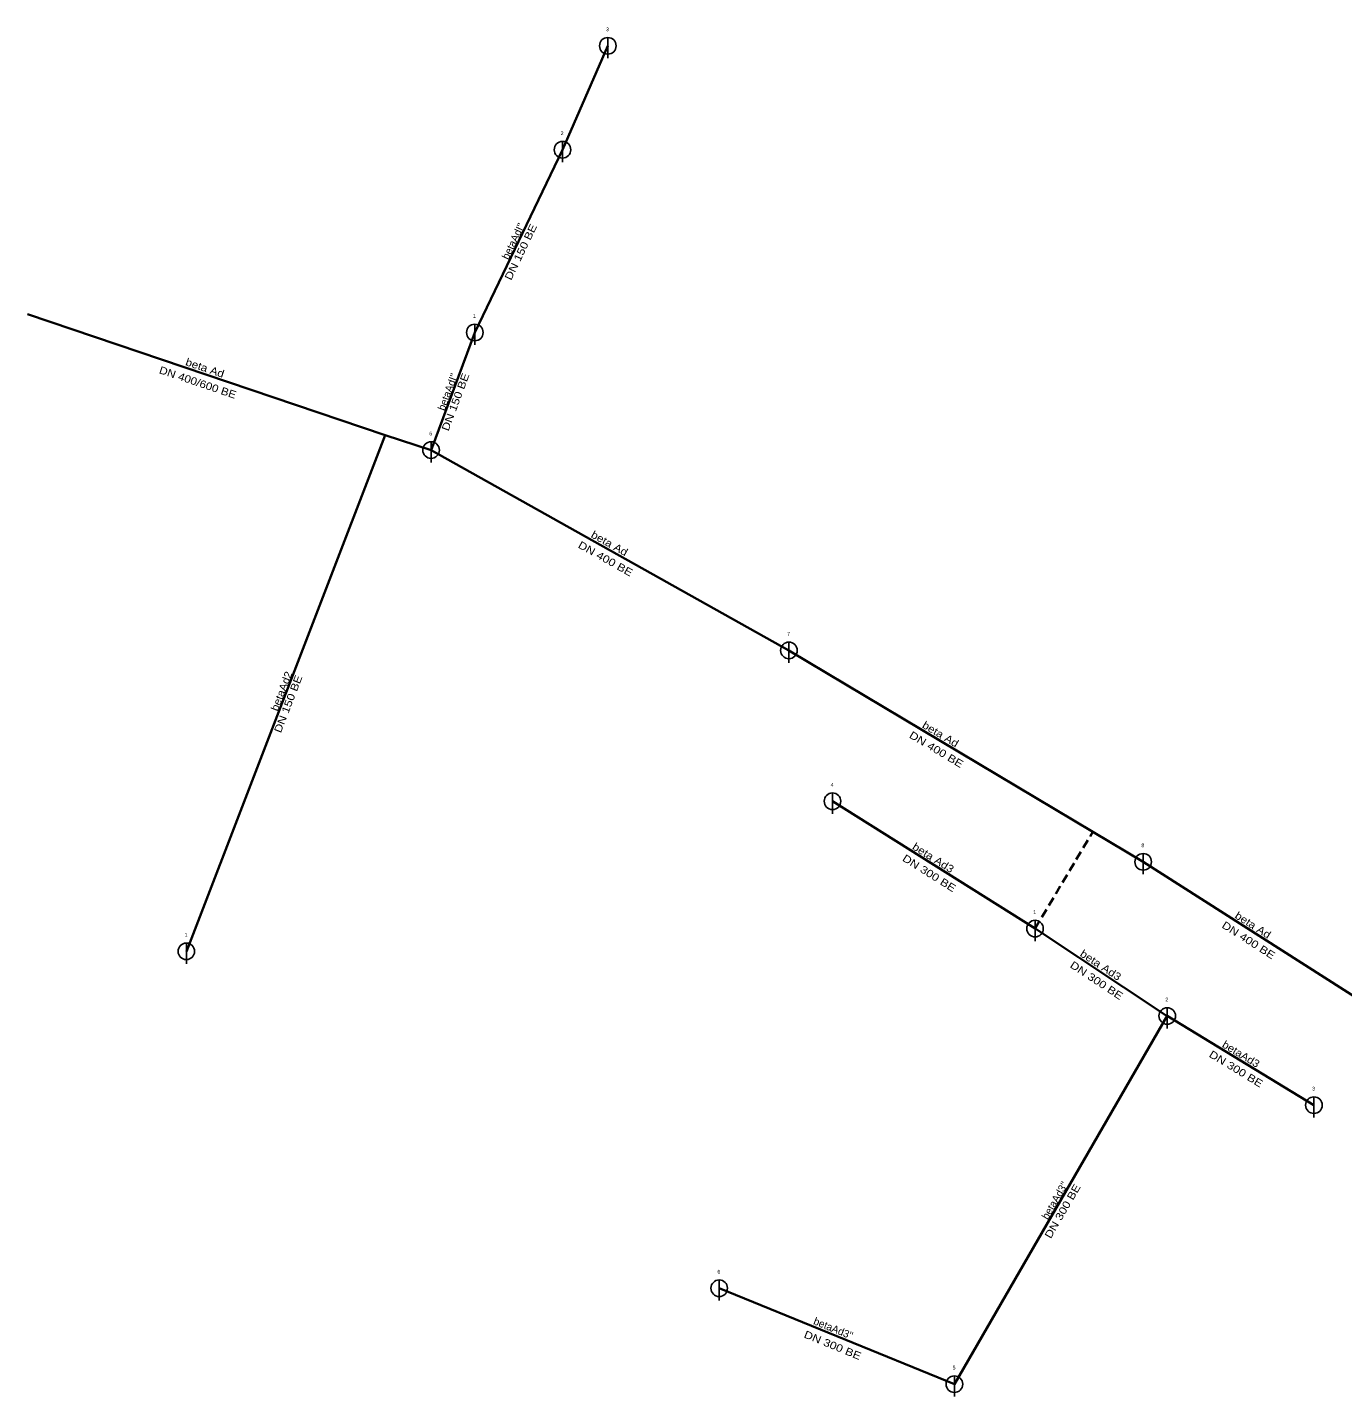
# Model space of a CAD drawing. Extents: x -463285 to -462962, y -1094714 to -1094478.
# Drawn here: x -463284.8 to -463126.1, y -1094643.4 to -1094478.2 of the extents above; entities that cross this region are included whole.
import ezdxf

# ---------------------------------------------------------------- set-up
doc = ezdxf.new("R2010")
doc.units = 0
doc.header["$LTSCALE"] = 0.36
doc.linetypes.add('MEDIUM_DASHED', pattern=[4.5, 3, -1.5])
for name, color, linetype, lineweight in [('1', 7, 'Continuous', 25), ('18', 7, 'MEDIUM_DASHED', 35), ('63', 7, 'Continuous', 35)]:
    doc.layers.add(name, color=color, linetype=linetype, lineweight=lineweight)
doc.layers.add('21', color=7, linetype='Continuous')
doc.layers.add('34', color=7, linetype='Continuous')

msp = doc.modelspace()

# ---------------------------------------------------------------- linework, layer by layer
at = {"layer": '1'}
for p, q in [((-463214.8, -1094479.44), (-463214.8, -1094481.94)), ((-463220.27, -1094491.98), (-463220.27, -1094494.48)), ((-463230.85, -1094514.03), (-463230.85, -1094516.53)), ((-463236.13, -1094528.22), (-463236.13, -1094530.72)), ((-463192.95, -1094552.4), (-463192.95, -1094554.9)), ((-463187.69, -1094570.6), (-463187.69, -1094573.1)), ((-463150.2, -1094577.91), (-463150.2, -1094580.41)), ((-463163.25, -1094585.961), (-463163.25, -1094588.461)), ((-463265.66, -1094588.71), (-463265.66, -1094591.21)), ((-463147.3, -1094596.51), (-463147.3, -1094599.01)), ((-463129.6, -1094607.27), (-463129.6, -1094609.77)), ((-463201.36, -1094629.36), (-463201.36, -1094631.86)), ((-463172.98, -1094640.94), (-463172.98, -1094643.44))]:
    msp.add_line(p, q, dxfattribs=at)
for centre in [(-463214.8, -1094480.44), (-463220.27, -1094492.98), (-463230.85, -1094515.03), (-463236.13, -1094529.22), (-463192.95, -1094553.4), (-463187.69, -1094571.6), (-463150.2, -1094578.91), (-463163.25, -1094586.961), (-463265.66, -1094589.71), (-463147.3, -1094597.51), (-463129.6, -1094608.27), (-463201.36, -1094630.36), (-463172.98, -1094641.94)]:
    msp.add_circle(centre, 1, dxfattribs=at)
at = {"layer": '18'}
msp.add_line((-463163.25, -1094586.961), (-463156.281, -1094575.282), dxfattribs=at)
at = {"layer": '63'}
for p, q in [((-463214.8, -1094480.44), (-463220.27, -1094492.98)), ((-463220.27, -1094492.98), (-463230.85, -1094515.03)), ((-463241.676, -1094527.409), (-463284.84, -1094512.83)), ((-463265.66, -1094589.71), (-463241.676, -1094527.409)), ((-463192.95, -1094553.4), (-463236.13, -1094529.22)), ((-463156.281, -1094575.282), (-463192.95, -1094553.4)), ((-463187.69, -1094571.6), (-463163.25, -1094586.961)), ((-463150.2, -1094578.91), (-463156.281, -1094575.282)), ((-463123.67, -1094595.84), (-463150.2, -1094578.91)), ((-463147.3, -1094597.511), (-463163.25, -1094586.961)), ((-463172.98, -1094641.94), (-463147.3, -1094597.51)), ((-463147.3, -1094597.51), (-463129.6, -1094608.27)), ((-463201.36, -1094630.36), (-463172.98, -1094641.94))]:
    msp.add_line(p, q, dxfattribs=at)
msp.add_lwpolyline([(-463230.85, -1094515.03), (-463236.13, -1094529.22), (-463241.676, -1094527.409)], dxfattribs=at)

# ---------------------------------------------------------------- texts
at = {"layer": '21'}
for s, rotation, width, p in [('DN 400/600 BE', 341.337, 1.15, (-463269.029, -1094519.93)), ('DN 400 BE', 330.752, 1.2, (-463218.481, -1094540.945)), ('DN 400 BE', 329.174, 1.2, (-463178.523, -1094563.868)), ('DN 300 BE', 327.85, 1.2, (-463179.347, -1094578.718)), ('DN 400 BE', 327.456, 1.2, (-463140.802, -1094586.786)), ('DN 300 BE', 326.518, 1.2, (-463159.119, -1094591.583))]:
    msp.add_text(s, height=0.91, rotation=rotation, dxfattribs=dict(at, width=width)).set_placement(p)
at = {"layer": '34', "width": 1.2}
for s, rotation, p in [('DN 150 BE', 64.367, (-463226.473, -1094508.812)), ('DN 150 BE', 69.59, (-463234.034, -1094526.998)), ('DN 150 BE', 68.945, (-463254.258, -1094563.426)), ('DN 300 BE', 328.704, (-463142.347, -1094602.385)), ('DN 300 BE', 59.973, (-463161.357, -1094624.45)), ('DN 300 BE', 337.803, (-463191.224, -1094636.278))]:
    msp.add_text(s, height=0.91, rotation=rotation, dxfattribs=at).set_placement(p)
at = {"layer": '63'}
for s, p in [('3', (-463215.016, -1094478.676)), ('2', (-463220.486, -1094491.216)), ('1', (-463231.066, -1094513.266)), ('6', (-463236.346, -1094527.456)), ('7', (-463193.166, -1094551.636)), ('4', (-463187.906, -1094569.836)), ('8', (-463150.416, -1094577.146)), ('1', (-463163.466, -1094585.197)), ('1', (-463265.876, -1094587.946)), ('2', (-463147.516, -1094595.746)), ('3', (-463129.816, -1094606.506)), ('6', (-463201.576, -1094628.596)), ('5', (-463173.196, -1094640.176))]:
    msp.add_text(s, height=0.455, dxfattribs=at).set_placement(p)
for s, rotation, p in [("betaAdI''", 64.367, (-463226.806, -1094506.32)), ("betaAdI''", 69.59, (-463234.494, -1094524.543)), ("betaAd3''", 59.973, (-463161.711, -1094622.162)), ("betaAd3''", 337.803, (-463190.078, -1094634.681))]:
    msp.add_text(s, height=0.91, rotation=rotation, dxfattribs=at).set_placement(p)
for s, rotation, width, p in [('beta Ad', 341.337, 1.15, (-463265.844, -1094518.963)), ('beta Ad', 330.752, 1.15, (-463216.921, -1094539.694)), ('betaAd2', 68.945, 1.1, (-463254.64, -1094560.804)), ('beta Ad', 329.174, 1.15, (-463176.959, -1094562.66)), ('beta Ad3', 327.85, 1.15, (-463178.147, -1094577.315)), ('beta Ad', 327.456, 1.15, (-463139.236, -1094585.624)), ('beta Ad3', 326.518, 1.15, (-463157.913, -1094590.208)), ('betaAd3', 328.704, 1.1, (-463140.763, -1094601.201))]:
    msp.add_text(s, height=0.91, rotation=rotation, dxfattribs=dict(at, width=width)).set_placement(p)

doc.saveas('drawing.dxf')
